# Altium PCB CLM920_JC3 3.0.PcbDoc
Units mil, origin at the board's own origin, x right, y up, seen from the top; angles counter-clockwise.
Board outline 6000 x 4000 mil, 2 copper layers (Top, Bottom), stack 12.7 mil thick; 1 components, 0 nets, 144 pads, 0 vias.
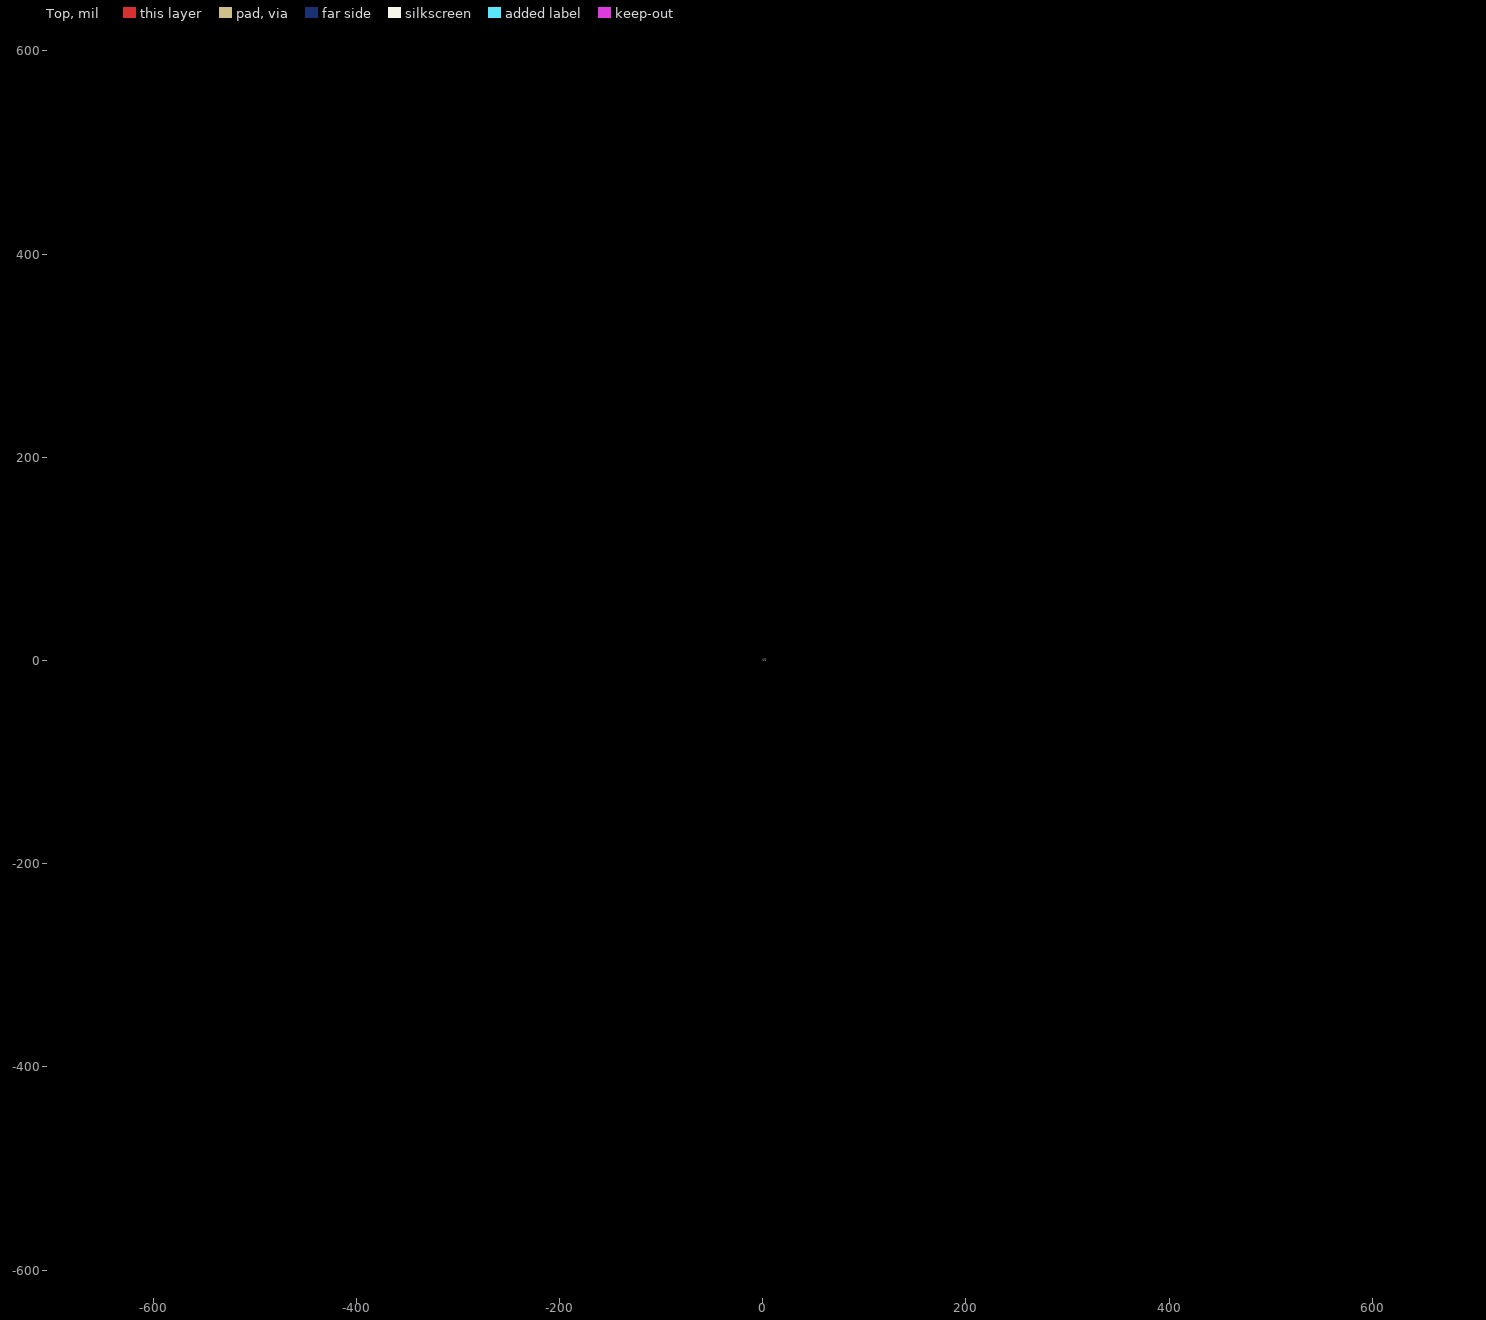
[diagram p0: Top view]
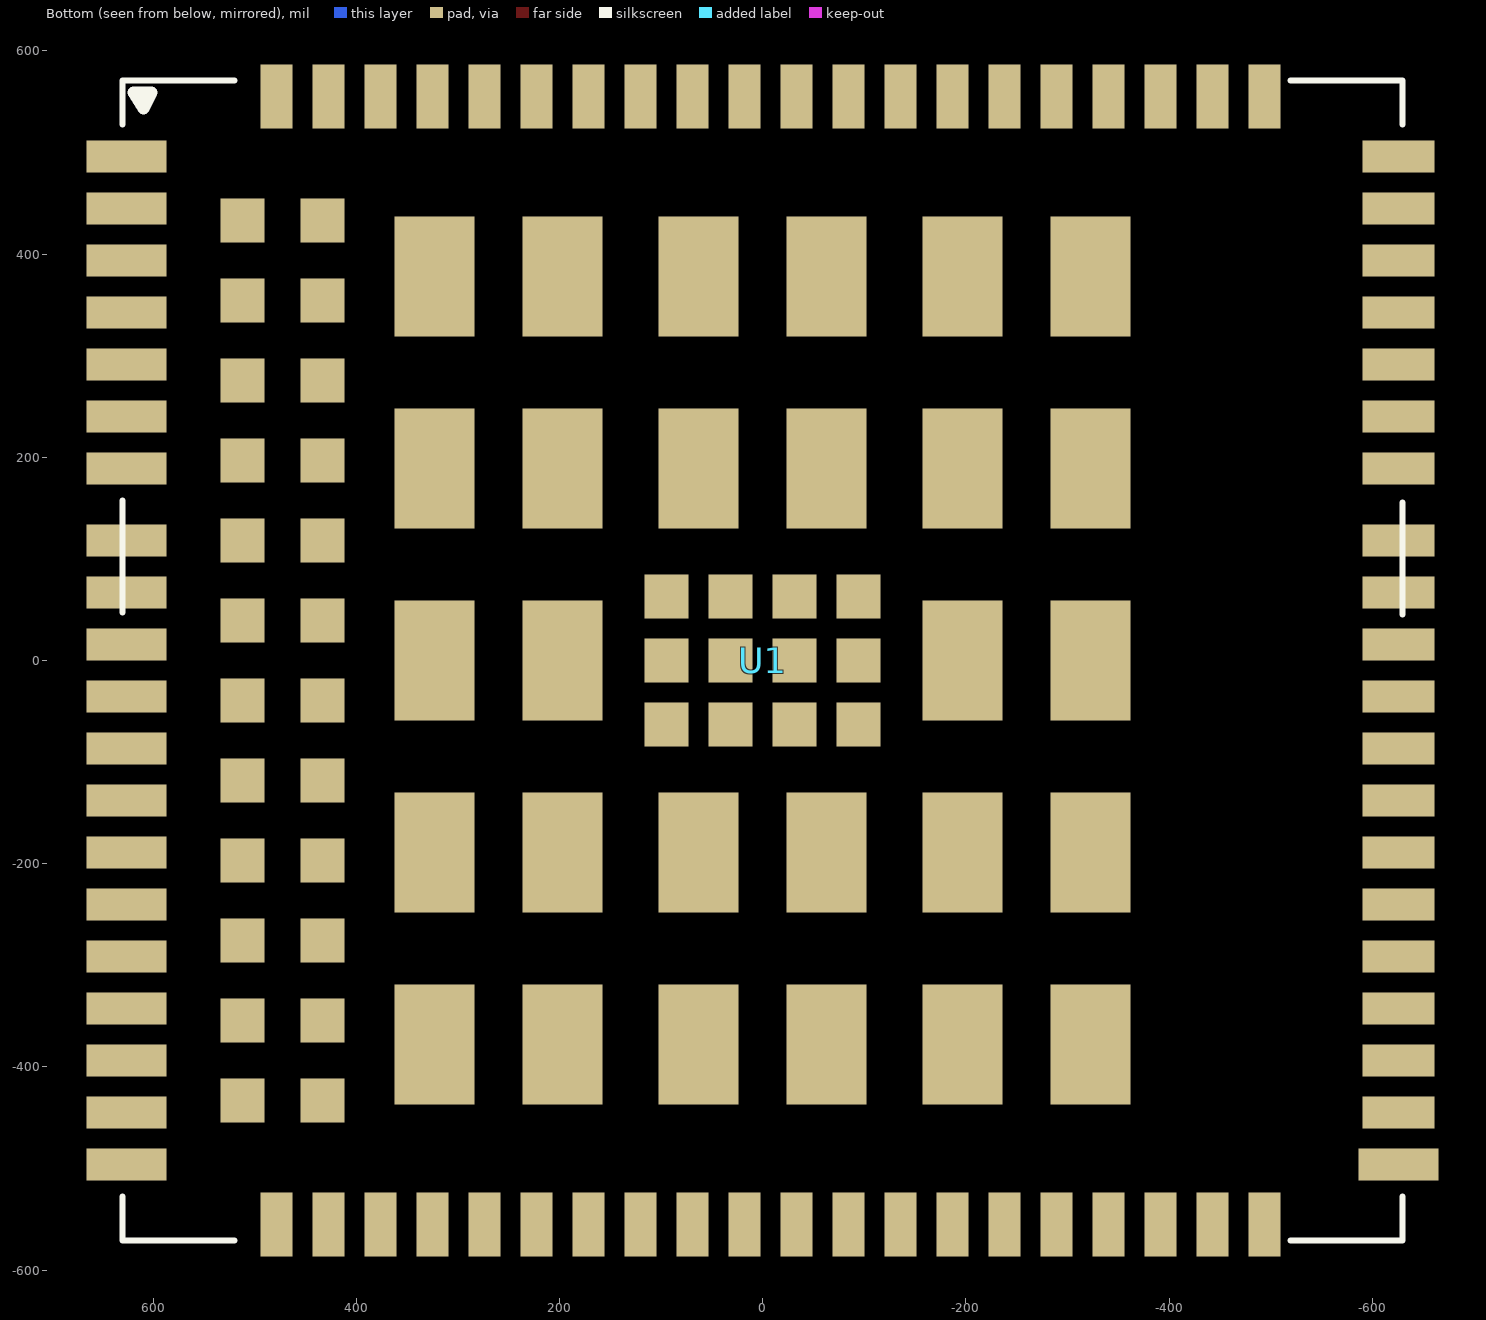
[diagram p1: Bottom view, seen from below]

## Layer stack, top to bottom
Solder Mask Top: solder mask 0.4, Solder Resist, Dk 3.5
Top: signal copper 1.35
Dielectric 1: dielectric 10, FR-4, Dk 4.3
Bottom: signal copper 1.35
Solder Mask Bottom: solder mask 0.4, Solder Resist, Dk 3.5

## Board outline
-9000,-9000 -3000,-9000 -3000,-5000 -9000,-5000

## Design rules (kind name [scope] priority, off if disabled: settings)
Clearance "Clearance - Default - DEFAULT- SMD" [IsVia vs IsSMTPin] p1: gap=6
Clearance "Clearance - Default - DEFAULT - Via" [IsVia vs IsVia] p2: gap=6
Clearance "Clearance - Default - DEFAULT - Net" [All] p3: gap=6 except(10: Text-Text)
ComponentClearance "ComponentClearance - Default - DEFAULT" [All] p1: gap=6 collisioncheckmode=3 verticalgap=10 showdistances=FALSE
FanoutControl Fanout_Small [(CompPinCount < 5)] p3: bgadir=Out bgaviamode=Centered fanoutstyle=Auto fanoutdirection=OutThenIn viagrid=1 // Fanout_Small (Default Rule)
FanoutControl Fanout_SOIC [IsSOIC] p4: bgadir=Out bgaviamode=Centered fanoutstyle=Auto fanoutdirection=Alternating viagrid=1 // Fanout_SOIC (Default Rule)
HoleToHoleClearance "HoleToHoleClearance - Default - DEFAULT" [All] p1: gap=6 allowstackedmicrovias=TRUE
Length "Default Length" [All] p1: maxlimit=50000 minlimit=0
MaxMinImpedance "Default Impedance" [All] p1: minimum=50.00 maximum=150.0
ParallelSegment "Default Parallel Segment Adjasent" [All] p1: limit=1000 gap=200
ParallelSegment "Default Parallel Segment Same Layer" [All] p2: limit=1000 gap=200
PlaneConnect "Default PlaneConnect" [All] p1: planeconnectstyle=Relief reliefexpansion=20 reliefentries=0 reliefconductorwidth=15 reliefairgap=10
PolygonConnect "PolygonConnect - Default SMT" [IsSMTPin] p1: connectstyle=Relief reliefconductorwidth=10 reliefentries=4 polygonreliefangle="45 Angle" airgapwidth=10
PolygonConnect "PolygonConnect - Default Pad" [All] p2: connectstyle=Relief reliefconductorwidth=15 reliefentries=4 polygonreliefangle="45 Angle" airgapwidth=10
RoutingLayers "RoutingLayers - Default - DEFAULT" [All] p1: top layer_v5=TRUE bottom layer_v5=TRUE
RoutingPriority "RoutingPriority - Default - DEFAULT" [All] p1: routingpriority=3
RoutingTopology "Default Routing Topology" [All] p1: topology=Shortest
RoutingVias "RoutingVias - Default - DEFAULT" [All] p1: holewidth=37 width=55 viastyle="Through Hole" minholewidth=37 minwidth=55 maxholewidth=37 maxwidth=55
SMDToCorner "SMDToCorner - Default - DEFAULT" [All] p1: distance=60000
SolderMaskExpansion [All] p1: expansion=4
Width "Default Width" [All] p1: maxlimit=12 minlimit=12 preferedwidth=12
20 further rules are at their usual default settings.

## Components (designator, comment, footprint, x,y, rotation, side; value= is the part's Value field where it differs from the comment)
U1 "IF_LCC_144P_DEMO" IF_LCC_144P_DEMO 0,0 r0 top

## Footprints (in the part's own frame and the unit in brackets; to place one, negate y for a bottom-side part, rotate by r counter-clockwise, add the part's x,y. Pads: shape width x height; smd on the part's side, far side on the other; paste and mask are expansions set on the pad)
IF_LCC_144P_DEMO [mm]
  rect 2x0.8 smd far side mask+0.05: 1(15.9,12.6) 2(15.9,11.3) 3(15.9,10) 4(15.9,8.7) 5(15.9,7.4) 6(15.9,6.1) 7(15.9,4.8) 8(15.9,0.4) 9(15.9,-0.9) 10(15.9,-2.2) 11(15.9,-3.5) 12(15.9,-4.8) 13(15.9,-6.1) 14(15.9,-7.4) 15(15.9,-8.7) 16(15.9,-10) 17(15.9,-11.3) 18(15.9,-12.6) 37(-15.9,-12.6) 141(15.9,3) 142(15.9,1.7)
  rect 0.8x1.6 smd far side: 19(9.55,-14.1) 20(8.25,-14.1) 21(6.95,-14.1) 22(5.65,-14.1) 23(4.35,-14.1) 24(3.05,-14.1) 25(1.75,-14.1) 26(0.45,-14.1) 27(-0.85,-14.1) 28(-2.15,-14.1) 29(-3.45,-14.1) 30(-4.75,-14.1) 31(-6.05,-14.1) 32(-7.35,-14.1) 33(-8.65,-14.1) 34(-9.95,-14.1) 35(-11.25,-14.1) 36(-12.55,-14.1) 55(-12.55,14.1) 56(-11.25,14.1) 57(-9.95,14.1) 58(-8.65,14.1) 59(-7.35,14.1) 60(-6.05,14.1) 61(-4.75,14.1) 62(-3.45,14.1) 63(-2.15,14.1) 64(-0.85,14.1) 65(0.45,14.1) 66(1.75,14.1) 67(3.05,14.1) 68(4.35,14.1) 69(5.65,14.1) 70(6.95,14.1) 71(8.25,14.1) 72(9.55,14.1) 113(10.85,14.1) 114(12.15,14.1) 115(10.85,-14.1) 116(12.15,-14.1)
  rect 1.8x0.8 smd far side mask+0.05: 38(-15.9,-11.3) 39(-15.9,-10) 40(-15.9,-8.7) 41(-15.9,-7.4) 42(-15.9,-6.1) 43(-15.9,-4.8) 44(-15.9,-3.5) 45(-15.9,-2.2) 46(-15.9,-0.9) 47(-15.9,0.4) 48(-15.9,4.8) 49(-15.9,6.1) 50(-15.9,7.4) 51(-15.9,8.7) 52(-15.9,10) 53(-15.9,11.3) 54(-15.9,12.6) 143(-15.9,3) 144(-15.9,1.7)
  rect 1.1x1.1 smd far side mask+0.05: 73(-2.4,1.6) 74(-2.4,0) 75(-2.4,-1.6) 76(-0.8,1.6) 77(-0.8,0) 78(-0.8,-1.6) 79(0.8,1.6) 80(0.8,0) 81(0.8,-1.6) 82(2.4,1.6) 83(2.4,0) 84(2.4,-1.6) 117(11,11) 118(11,9) 119(11,7) 120(11,5) 121(11,3) 122(11,1) 123(11,-1) 124(11,-3) 125(11,-5) 126(11,-7) 127(11,-9) 128(11,-11) 129(13,11) 130(13,9) 131(13,7) 132(13,5) 133(13,3) 134(13,1) 135(13,-1) 136(13,-3) 137(13,-5) 138(13,-7) 139(13,-9) 140(13,-11)
  rect 2x3 smd far side mask+0.05: 85(-8.2,9.6) 86(-8.2,4.8) 87(-8.2,0) 88(-8.2,-4.8) 89(-8.2,-9.6) 90(-5,9.6) 91(-5,4.8) 92(-5,0) 93(-5,-4.8) 94(-5,-9.6) 95(-1.6,9.6) 96(-1.6,4.8) 97(-1.6,-4.8) 98(-1.6,-9.6) 99(1.6,9.6) 100(1.6,4.8) 101(1.6,-4.8) 102(1.6,-9.6) 103(5,9.6) 104(5,4.8) 105(5,0) 106(5,-4.8) 107(5,-9.6) 108(8.2,9.6) 109(8.2,4.8) 110(8.2,0) 111(8.2,-4.8) 112(8.2,-9.6)

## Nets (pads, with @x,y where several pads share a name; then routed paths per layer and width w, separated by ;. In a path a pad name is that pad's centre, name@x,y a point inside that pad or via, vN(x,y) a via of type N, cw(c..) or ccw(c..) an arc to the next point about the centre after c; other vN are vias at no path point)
pads on no net: U1.1 U1.2 U1.3 U1.4 U1.5 U1.6 U1.7 U1.8 U1.9 U1.10 U1.11 U1.12 U1.13 U1.14 U1.15 U1.16 U1.17 U1.18 U1.19 U1.20 U1.21 U1.22 U1.23 U1.24 U1.25 U1.26 U1.27 U1.28 U1.29 U1.30 U1.31 U1.32 U1.33 U1.34 U1.35 U1.36 U1.37 U1.38 U1.39 U1.40 U1.41 U1.42 U1.43 U1.44 U1.45 U1.46 U1.47 U1.48 U1.49 U1.50 U1.51 U1.52 U1.53 U1.54 U1.55 U1.56 U1.57 U1.58 U1.59 U1.60 U1.61 U1.62 U1.63 U1.64 U1.65 U1.66 U1.67 U1.68 U1.69 U1.70 U1.71 U1.72 U1.73 U1.74 U1.75 U1.76 U1.77 U1.78 U1.79 U1.80 U1.81 U1.82 U1.83 U1.84 U1.85 U1.86 U1.87 U1.88 U1.89 U1.90 U1.91 U1.92 U1.93 U1.94 U1.95 U1.96 U1.97 U1.98 U1.99 U1.100 U1.101 U1.102 U1.103 U1.104 U1.105 U1.106 U1.107 U1.108 U1.109 U1.110 U1.111 U1.112 U1.113 U1.114 U1.115 U1.116 U1.117 U1.118 U1.119 U1.120 U1.121 U1.122 U1.123 U1.124 U1.125 U1.126 U1.127 U1.128 U1.129 U1.130 U1.131 U1.132 U1.133 U1.134 U1.135 U1.136 U1.137 U1.138 U1.139 U1.140 U1.141 U1.142 U1.143 U1.144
